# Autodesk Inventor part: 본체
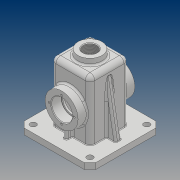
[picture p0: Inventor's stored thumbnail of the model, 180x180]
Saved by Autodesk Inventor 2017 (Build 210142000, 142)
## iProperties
Part Number: 본체
Material: 일반
Document SubType Name: Modeling
Designer: 20
Density: 1 g/cm^3
Appearance: 기본값
Mass: 293.223 g
Surface Area: 897.812 cm^2
Volume: 293.223 cm^3
Author: 20
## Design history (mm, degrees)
sketch "스케치1"
  geometry: L1 (-32.5, 32.5)-(32.5, 32.5); L2 (32.5, 32.5)-(32.5, -32.5); L3 (32.5, -32.5)-(-32.5, -32.5); L4 (-32.5, -32.5)-(-32.5, 32.5); L5 (-32.5, 32.5)-(32.5, -32.5); L6 (32.5, 32.5)-(-32.5, -32.5); 1 further point
  constraints: 12 end point, 2 midpoint, 2 parallel, 1 horizontal, 1 perpendicular
  dimensions: "d0" = 65 distance of L2.end L3.end; "d1" = 65 distance of L1.end L2.end
extrude "돌출1" new body sketch "스케치1" stored distance "d2" = 110; taper "d3" = 0 deg
fillet "모깎기1" dims "d4" = 8
fillet "모깎기2" dims "d5" = 8
feature "쉘1" dims "d6" = 5
sketch "스케치2"
  geometry: L1 (60, -60)-(-60, -60); L2 (-60, -60)-(-60, 60); L3 (-60, 60)-(60, 60); L4 (60, 60)-(60, -60); L5 (60, -60)-(-60, 60); L6 (-60, -60)-(60, 60); L7 (24.5, -27.5)-(-24.5, -27.5) reference; L8 (27.5, 24.5)-(27.5, -24.5) reference; L9 (-24.5, 27.5)-(24.5, 27.5) reference; L10 (-27.5, -24.5)-(-27.5, 24.5) reference; A1 r 3 centre (24.5, -24.5) between (24.5, -27.5) and (27.5, -24.5) reference; A2 r 3 centre (24.5, 24.5) between (27.5, 24.5) and (24.5, 27.5) reference; A3 r 3 centre (-24.5, 24.5) between (-24.5, 27.5) and (-27.5, 24.5) reference; A4 r 3 centre (-24.5, -24.5) between (-27.5, -24.5) and (-24.5, -27.5) reference; 1 further point
  constraints: 12 end point, 2 midpoint, 2 parallel, 1 horizontal, 1 perpendicular
  dimensions: "d7" = 120 distance of L2.end L3.end; "d8" = 120 distance of L1.end L2.end
extrude "돌출2" join sketch "스케치2" distance "d9" = 10; taper "d10" = 0 deg
sketch "스케치3"
  geometry: C1 r 27.5 at (24.5, -47); 1 further point
  constraints: 1 centre point, 1 coincident
  dimensions: "d11" = 55 diameter of C1
extrude "돌출3" join sketch "스케치3" distance "d12" = 15; taper "d13" = 0 deg
sketch "스케치4"
  geometry: C1 r 17.5 at (0, 0); 1 further point
  constraints: 1 centre point, 1 coincident
  dimensions: "d14" = 35 diameter of C1
extrude "돌출4" cut sketch "스케치4" distance "d15" = 17; taper "d16" = 0 deg
sketch "스케치5"
  geometry: C1 r 15 at (0, 0); 1 further point
  constraints: 1 centre point, 1 coincident
  dimensions: "d17" = 30 diameter of C1
extrude "돌출5" cut sketch "스케치5" stored distance "d18" = 17; taper "d19" = 0 deg
sketch "스케치6"
  geometry: L1 (-32.5, -27.5)-(-47.5, -27.5) reference; L2 (60, -45)-(-60, -45) reference; L3 (-42.5, -27.5)-(-42.5, -45); L4 (-32.5, -12.49)-(-32.5, -45) reference; 1 further point
  constraints: 2 end point, 2 point on line, 1 vertical
  dimensions: "d20" = 10 distance between parallel lines of L4 L3
feature "리브1" sketch "스케치6" dims "d21" = 1, "d22" = 6, "d23" = 0, "d24" = 0, "d25" = 1, "d26" = 1
sketch "스케치7"
  geometry: L1 (-60, -45)-(60, -45) reference; L2 (48, -45)-(40.418, -2); L3 (60, -55)-(60, -45) reference; 1 further point
  constraints: 2 end point, 1 point on line
  dimensions: "d27" = 10 deg angle of L2 L3; "d28" = 12 distance from line of L2.start L3; "d29" = 43 vertical distance of L2.start L2.end
feature "리브2" sketch "스케치7" dims "d30" = 1, "d31" = 10, "d32" = 0, "d33" = 0, "d34" = 1, "d35" = 1
node "작업 평면1"
sketch "스케치8"
  geometry: C1 r 20 at (0, 0); 1 further point
  constraints: 1 centre point, 1 coincident
  dimensions: "d37" = 40 diameter of C1
extrude "돌출6" join sketch "스케치8" stored distance "d38" = 17; taper "d39" = 0 deg
hole "구멍1" diameter "d42" = 22.835; stored, may be unused: countersink angle "d46" = 90 deg, drill point angle "d48" = 118 deg; dims "d40" = 10, "d41" = 10, "d43" = 50, "d44" = 4, "d45" = 2, "d47" = 59.3
chamfer "모따기1" distance "d49" = 1; stored, may be unused: second distance "d50" = 2, angle "d51" = 45 deg
feature "면 기울기1" dims angle "d52" = 5 deg
sketch "스케치9"
  geometry: L1 (-60, -60)-(60, -60) reference; L2 (-60, 60)-(-60, -60) reference; C1 r 5 at (-47.5, -47.5); 1 further point
  constraints: 1 centre point
  dimensions: "d53" = 10 diameter of C1; "d54" = 12.5 distance from line of L1 C1.centre; "d55" = 12.5 distance from line of C1.centre L2
extrude "돌출7" cut sketch "스케치9" distance "d56" = 17; taper "d57" = 0 deg
chamfer "모따기2" distance "d58" = 10; stored, may be unused: second distance "d59" = 2, angle "d60" = 45 deg
fillet "모깎기3" dims "d67" = 3
fillet "모깎기4" dims "d68" = 3
fillet "모깎기5" dims "d69" = 1
fillet "모깎기6" dims "d70" = 3
node "작업 평면2"
sketch "스케치10"
  geometry: L1 (57, 0)-(57, 91) reference; L2 (4.5, -18)-(44.5, -18) reference; 2 further points
  constraints: 1 other
  dimensions: "d73" = 32.5 distance from line of point (24.5, 8) L1; "d74" = 26 distance from line of L2 point (24.5, 8)
feature "엠보싱1" sketch "스케치10" dims "d75" = 0.5, "d76" = 0
sketch "스케치11"
  geometry: 2 further points
  constraints: 1 vertical alignment
  dimensions: "d77" = 21 distance of point (0, 0) point (0, 21)
hole "구멍2" sketch "스케치11" at (0, 21) diameter "d78" = 3.242; stored, may be unused: countersink angle "d82" = 90 deg, drill point angle "d84" = 118 deg; dims "d79" = 8, "d80" = 4, "d81" = 2, "d83" = 10
fillet "모깎기8" dims "d88" = 0.3
fillet "모깎기9" dims "d89" = 3
node "솔리드1"
mirror "미러1"
mirror "미러2"
mirror "미러3"
pattern_linear "직사각형 패턴1" dims "d63" = 95, "d66" = 95
pattern_circular "원형 패턴1" dims angle "d86" = 360 deg
mirror "미러4"
